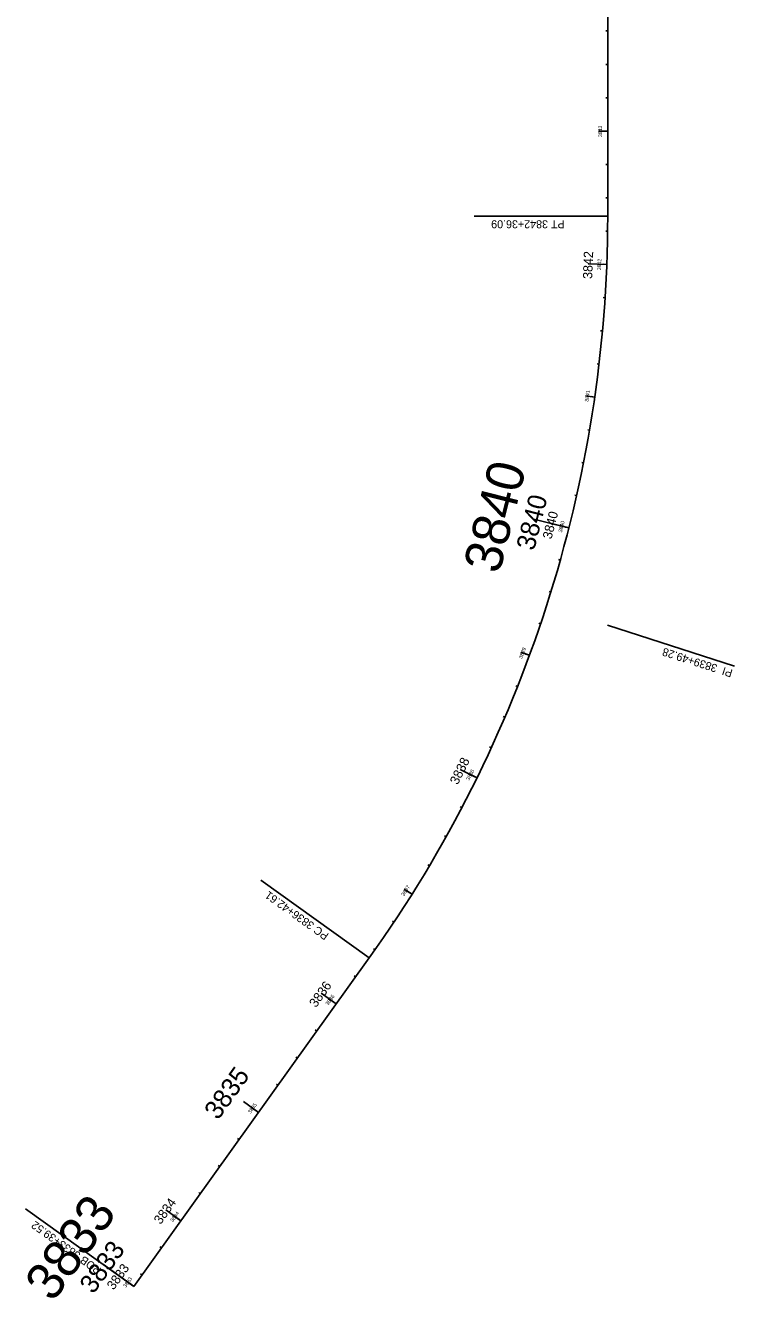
# Model space of a CAD drawing. Extents: x 536709 to 765910, y 180209 to 191282.
# Drawn here: x 594323 to 594855, y 182695 to 183650 of the extents above; entities that cross this region are included whole.
import ezdxf

# ---------------------------------------------------------------- set-up
doc = ezdxf.new("R2010")
doc.units = 0
for name, color, linetype in [('P_ALI_100', 7, 'Continuous'), ('P_ALI_100_Sta', 7, 'Continuous'), ('P_ALI_100_Tic', 7, 'Continuous'), ('P_ALI_20', 7, 'Continuous'), ('P_ALI_200', 7, 'Continuous'), ('P_ALI_200_Sta', 7, 'Continuous'), ('P_ALI_200_Tic', 7, 'Continuous'), ('P_ALI_20_Sta', 7, 'Continuous'), ('P_ALI_20_Tic', 7, 'Continuous'), ('P_ALI_50', 7, 'Continuous'), ('P_ALI_50_CPIData', 7, 'Continuous'), ('P_ALI_50_PIData', 7, 'Continuous'), ('P_ALI_50_Sta', 7, 'Continuous'), ('P_ALI_50_Tic', 7, 'Continuous')]:
    doc.layers.add(name, color=color, linetype=linetype)

msp = doc.modelspace()

# ---------------------------------------------------------------- linework, layer by layer
at = {"layer": 'P_ALI_100'}
for p, q in [((594759.83, 183506.52), (594760.03, 184249.13)), ((594759.83, 183506.52), (594760.03, 184249.13)), ((594759.83, 183506.52), (594760.03, 184249.13)), ((594759.83, 183506.52), (594760.03, 184249.13)), ((594759.83, 183506.52), (594760.03, 184249.13)), ((594759.83, 183506.52), (594760.03, 184249.13)), ((594759.83, 183506.52), (594760.03, 184249.13)), ((594759.83, 183506.52), (594760.03, 184249.13)), ((594759.83, 183506.52), (594760.03, 184249.13)), ((594759.83, 183506.52), (594760.03, 184249.13)), ((594759.83, 183506.52), (594760.03, 184249.13)), ((594404.59, 182704.19), (594581.13, 182950.56)), ((594404.59, 182704.19), (594581.13, 182950.56)), ((594404.59, 182704.19), (594581.13, 182950.56)), ((594404.59, 182704.19), (594581.13, 182950.56)), ((594404.59, 182704.19), (594581.13, 182950.56)), ((594404.59, 182704.19), (594581.13, 182950.56)), ((594404.59, 182704.19), (594581.13, 182950.56)), ((594404.59, 182704.19), (594581.13, 182950.56)), ((594404.59, 182704.19), (594581.13, 182950.56)), ((594404.59, 182704.19), (594581.13, 182950.56)), ((594404.59, 182704.19), (594581.13, 182950.56))]:
    msp.add_line(p, q, dxfattribs=at)
msp.add_arc((593804.9, 183506.77), 954.93, 324.37625, 359.98472, dxfattribs=at)
msp.add_arc((593804.9, 183506.77), 954.93, 324.37625, 359.98472, dxfattribs=at)
msp.add_arc((593804.9, 183506.77), 954.93, 324.37625, 359.98472, dxfattribs=at)
msp.add_arc((593804.9, 183506.77), 954.93, 324.37625, 359.98472, dxfattribs=at)
msp.add_arc((593804.9, 183506.77), 954.93, 324.37625, 359.98472, dxfattribs=at)
msp.add_arc((593804.9, 183506.77), 954.93, 324.37625, 359.98472, dxfattribs=at)
msp.add_arc((593804.9, 183506.77), 954.93, 324.37625, 359.98472, dxfattribs=at)
msp.add_arc((593804.9, 183506.77), 954.93, 324.37625, 359.98472, dxfattribs=at)
msp.add_arc((593804.9, 183506.77), 954.93, 324.37625, 359.98472, dxfattribs=at)
msp.add_arc((593804.9, 183506.77), 954.93, 324.37625, 359.98472, dxfattribs=at)
msp.add_arc((593804.9, 183506.77), 954.93, 324.37625, 359.98472, dxfattribs=at)
at = {"layer": 'P_ALI_100_Tic'}
for points in [[(594752.85, 183570.43), (594759.85, 183570.43)], [(594752.15, 183470.7), (594759.14, 183470.44)], [(594743.19, 183371.89), (594750.12, 183370.89)], [(594717.16, 183276.26), (594730.74, 183272.83)], [(594694.64, 183179.76), (594701.21, 183177.34)], [(594655.58, 183088.54), (594661.87, 183085.46)], [(594607.21, 183001.91), (594613.13, 182998.19)], [(594550.62, 182920), (594556.31, 182915.92)], [(594486.68, 182842.79), (594498.06, 182834.64)], [(594434.13, 182757.43), (594439.82, 182753.35)], [(594393.21, 182712.34), (594404.59, 182704.19)], [(594398.9, 182708.27), (594404.59, 182704.19)]]:
    msp.add_lwpolyline(points, dxfattribs=at)
at = {"layer": 'P_ALI_20'}
for p, q in [((594759.83, 183506.52), (594760.03, 184249.13)), ((594404.59, 182704.19), (594581.13, 182950.56))]:
    msp.add_line(p, q, dxfattribs=at)
msp.add_arc((593804.9, 183506.77), 954.93, 324.37625, 359.98472, dxfattribs=at)
at = {"layer": 'P_ALI_200'}
for p, q in [((594759.83, 183506.52), (594760.03, 184249.13)), ((594759.83, 183506.52), (594760.03, 184249.13)), ((594759.83, 183506.52), (594760.03, 184249.13)), ((594759.83, 183506.52), (594760.03, 184249.13)), ((594759.83, 183506.52), (594760.03, 184249.13)), ((594759.83, 183506.52), (594760.03, 184249.13)), ((594759.83, 183506.52), (594760.03, 184249.13)), ((594759.83, 183506.52), (594760.03, 184249.13)), ((594759.83, 183506.52), (594760.03, 184249.13)), ((594759.83, 183506.52), (594760.03, 184249.13)), ((594404.59, 182704.19), (594581.13, 182950.56)), ((594404.59, 182704.19), (594581.13, 182950.56)), ((594404.59, 182704.19), (594581.13, 182950.56)), ((594404.59, 182704.19), (594581.13, 182950.56)), ((594404.59, 182704.19), (594581.13, 182950.56)), ((594404.59, 182704.19), (594581.13, 182950.56)), ((594404.59, 182704.19), (594581.13, 182950.56)), ((594404.59, 182704.19), (594581.13, 182950.56)), ((594404.59, 182704.19), (594581.13, 182950.56)), ((594404.59, 182704.19), (594581.13, 182950.56))]:
    msp.add_line(p, q, dxfattribs=at)
msp.add_arc((593804.9, 183506.77), 954.93, 324.37625, 359.98472, dxfattribs=at)
msp.add_arc((593804.9, 183506.77), 954.93, 324.37625, 359.98472, dxfattribs=at)
msp.add_arc((593804.9, 183506.77), 954.93, 324.37625, 359.98472, dxfattribs=at)
msp.add_arc((593804.9, 183506.77), 954.93, 324.37625, 359.98472, dxfattribs=at)
msp.add_arc((593804.9, 183506.77), 954.93, 324.37625, 359.98472, dxfattribs=at)
msp.add_arc((593804.9, 183506.77), 954.93, 324.37625, 359.98472, dxfattribs=at)
msp.add_arc((593804.9, 183506.77), 954.93, 324.37625, 359.98472, dxfattribs=at)
msp.add_arc((593804.9, 183506.77), 954.93, 324.37625, 359.98472, dxfattribs=at)
msp.add_arc((593804.9, 183506.77), 954.93, 324.37625, 359.98472, dxfattribs=at)
msp.add_arc((593804.9, 183506.77), 954.93, 324.37625, 359.98472, dxfattribs=at)
at = {"layer": 'P_ALI_200_Tic'}
for points in [[(594745.15, 183470.97), (594759.14, 183470.44)], [(594745.15, 183470.97), (594759.14, 183470.44)], [(594703.59, 183279.69), (594730.74, 183272.83)], [(594703.59, 183279.69), (594730.74, 183272.83)], [(594649.3, 183091.63), (594661.87, 183085.46)], [(594649.3, 183091.63), (594661.87, 183085.46)], [(594544.93, 182924.08), (594556.31, 182915.92)], [(594544.93, 182924.08), (594556.31, 182915.92)], [(594428.44, 182761.51), (594439.82, 182753.35)], [(594428.44, 182761.51), (594439.82, 182753.35)], [(594381.83, 182720.5), (594404.59, 182704.19)], [(594381.83, 182720.5), (594404.59, 182704.19)], [(594393.21, 182712.34), (594404.59, 182704.19)], [(594393.21, 182712.34), (594404.59, 182704.19)]]:
    msp.add_lwpolyline(points, dxfattribs=at)
at = {"layer": 'P_ALI_20_Tic'}
for points in [[(594758.47, 183645.43), (594759.87, 183645.43)], [(594758.46, 183620.43), (594759.86, 183620.43)], [(594758.46, 183595.43), (594759.86, 183595.43)], [(594757.05, 183570.43), (594759.85, 183570.43)], [(594758.44, 183545.43), (594759.84, 183545.43)], [(594758.44, 183520.43), (594759.84, 183520.43)], [(594758.37, 183495.45), (594759.77, 183495.43)], [(594756.34, 183470.54), (594759.14, 183470.44)], [(594756.47, 183445.56), (594757.86, 183445.47)], [(594754.54, 183420.67), (594755.93, 183420.55)], [(594751.96, 183395.84), (594753.35, 183395.68)], [(594747.35, 183371.29), (594750.12, 183370.89)], [(594744.86, 183346.43), (594746.24, 183346.2)], [(594740.34, 183321.88), (594741.71, 183321.61)], [(594735.18, 183297.46), (594736.54, 183297.15)], [(594728.02, 183273.52), (594730.74, 183272.83)], [(594722.95, 183249.06), (594724.3, 183248.68)], [(594715.89, 183225.11), (594717.22, 183224.7)], [(594708.2, 183201.36), (594709.53, 183200.92)], [(594698.58, 183178.31), (594701.21, 183177.34)], [(594690.98, 183154.51), (594692.28, 183153.99)], [(594681.46, 183131.43), (594682.74, 183130.88)], [(594671.33, 183108.62), (594672.6, 183108.03)], [(594659.35, 183086.69), (594661.87, 183085.46)], [(594649.3, 183063.82), (594650.54, 183063.17)], [(594637.42, 183041.87), (594638.64, 183041.18)], [(594624.96, 183020.23), (594626.17, 183019.52)], [(594610.76, 182999.68), (594613.13, 182998.19)], [(594598.38, 182977.98), (594599.54, 182977.2)], [(594584.26, 182957.39), (594585.41, 182956.58)], [(594569.73, 182937.06), (594570.87, 182936.25)], [(594554.03, 182917.56), (594556.31, 182915.92)], [(594540.61, 182896.42), (594541.75, 182895.6)], [(594526.05, 182876.1), (594527.19, 182875.28)], [(594511.49, 182855.78), (594512.62, 182854.96)], [(594495.79, 182836.27), (594498.06, 182834.64)], [(594482.36, 182815.13), (594483.5, 182814.32)], [(594467.8, 182794.81), (594468.94, 182794)], [(594453.24, 182774.49), (594454.38, 182773.67)], [(594437.54, 182754.98), (594439.82, 182753.35)], [(594424.12, 182733.85), (594425.25, 182733.03)], [(594409.56, 182713.52), (594410.69, 182712.71)], [(594402.31, 182705.82), (594404.59, 182704.19)], [(594403.45, 182705), (594404.59, 182704.19)]]:
    msp.add_lwpolyline(points, dxfattribs=at)
at = {"layer": 'P_ALI_50'}
for p, q in [((594759.83, 183506.52), (594760.03, 184249.13)), ((594759.83, 183506.52), (594760.03, 184249.13)), ((594759.83, 183506.52), (594760.03, 184249.13)), ((594759.83, 183506.52), (594760.03, 184249.13)), ((594759.83, 183506.52), (594760.03, 184249.13)), ((594759.83, 183506.52), (594760.03, 184249.13)), ((594759.83, 183506.52), (594760.03, 184249.13)), ((594759.83, 183506.52), (594760.03, 184249.13)), ((594759.83, 183506.52), (594760.03, 184249.13)), ((594759.83, 183506.52), (594760.03, 184249.13)), ((594404.59, 182704.19), (594581.13, 182950.56)), ((594404.59, 182704.19), (594581.13, 182950.56)), ((594404.59, 182704.19), (594581.13, 182950.56)), ((594404.59, 182704.19), (594581.13, 182950.56)), ((594404.59, 182704.19), (594581.13, 182950.56)), ((594404.59, 182704.19), (594581.13, 182950.56)), ((594404.59, 182704.19), (594581.13, 182950.56)), ((594404.59, 182704.19), (594581.13, 182950.56)), ((594404.59, 182704.19), (594581.13, 182950.56)), ((594404.59, 182704.19), (594581.13, 182950.56))]:
    msp.add_line(p, q, dxfattribs=at)
msp.add_arc((593804.9, 183506.77), 954.93, 324.37625, 359.98472, dxfattribs=at)
msp.add_arc((593804.9, 183506.77), 954.93, 324.37625, 359.98472, dxfattribs=at)
msp.add_arc((593804.9, 183506.77), 954.93, 324.37625, 359.98472, dxfattribs=at)
msp.add_arc((593804.9, 183506.77), 954.93, 324.37625, 359.98472, dxfattribs=at)
msp.add_arc((593804.9, 183506.77), 954.93, 324.37625, 359.98472, dxfattribs=at)
msp.add_arc((593804.9, 183506.77), 954.93, 324.37625, 359.98472, dxfattribs=at)
msp.add_arc((593804.9, 183506.77), 954.93, 324.37625, 359.98472, dxfattribs=at)
msp.add_arc((593804.9, 183506.77), 954.93, 324.37625, 359.98472, dxfattribs=at)
msp.add_arc((593804.9, 183506.77), 954.93, 324.37625, 359.98472, dxfattribs=at)
msp.add_arc((593804.9, 183506.77), 954.93, 324.37625, 359.98472, dxfattribs=at)
at = {"layer": 'P_ALI_50_CPIData'}
msp.add_lwpolyline([(594759.75, 183199.84), (594854.95, 183169.24)], dxfattribs=at)
at = {"layer": 'P_ALI_50_PIData'}
for points in [[(594759.83, 183506.52), (594659.83, 183506.54)], [(594581.13, 182950.56), (594499.84, 183008.81)], [(594404.59, 182704.19), (594323.3, 182762.43)]]:
    msp.add_lwpolyline(points, dxfattribs=at)
at = {"layer": 'P_ALI_50_Tic'}
for points in [[(594756.35, 183570.43), (594759.85, 183570.43)], [(594752.15, 183470.7), (594759.14, 183470.44)], [(594746.65, 183371.39), (594750.12, 183370.89)], [(594723.95, 183274.55), (594730.74, 183272.83)], [(594697.93, 183178.55), (594701.21, 183177.34)], [(594655.58, 183088.54), (594661.87, 183085.46)], [(594610.17, 183000.05), (594613.13, 182998.19)], [(594550.62, 182920), (594556.31, 182915.92)], [(594495.22, 182836.68), (594498.06, 182834.64)], [(594434.13, 182757.43), (594439.82, 182753.35)], [(594398.9, 182708.27), (594404.59, 182704.19)], [(594401.74, 182706.23), (594404.59, 182704.19)]]:
    msp.add_lwpolyline(points, dxfattribs=at)

# ---------------------------------------------------------------- texts
at = {"layer": 'P_ALI_100_Sta'}
for s, rotation, p in [('3840', 75.81955, (594704.64, 183255.27)), ('3835', 54.37625, (594467.7, 182828.32)), ('3833', 54.37625, (594374.23, 182697.87))]:
    msp.add_text(s, height=14, rotation=rotation, dxfattribs=at).set_placement(p)
at = {"layer": 'P_ALI_200_Sta'}
for s, rotation, p in [('3840', 75.81955, (594678.54, 183237.7)), ('3840', 75.81955, (594678.54, 183237.7)), ('3833', 54.37625, (594343.87, 182691.56)), ('3833', 54.37625, (594343.87, 182691.56))]:
    msp.add_text(s, height=28, rotation=rotation, dxfattribs=at).set_placement(p)
at = {"layer": 'P_ALI_20_Sta'}
for s, rotation, p in [('3843', 89.98472, (594755.65, 183565.87)), ('3842', 87.81955, (594754.77, 183466.04)), ('3841', 81.81955, (594745.36, 183367.32)), ('3840', 75.81955, (594725.52, 183269.32)), ('3839', 69.81955, (594695.69, 183174.51)), ('3838', 63.81955, (594656.08, 183083.21)), ('3837', 57.81956, (594607.15, 182996.56)), ('3836', 54.37625, (594550.24, 182914.66)), ('3835', 54.37625, (594491.99, 182833.38)), ('3834', 54.37625, (594433.74, 182752.09)), ('3833', 54.37625, (594398.51, 182702.92))]:
    msp.add_text(s, height=2.8, rotation=rotation, dxfattribs=at).set_placement(p)
at = {"layer": 'P_ALI_50_CPIData'}
msp.add_text('PI  3839+49.28', height=6, rotation=162.18048, dxfattribs=at).set_placement((594854.04, 183166.38))
at = {"layer": 'P_ALI_50_PIData'}
for s, rotation, p in [('PT 3842+36.09', 179.98472, (594727.58, 183503.52)), ('PC 3836+42.61', 144.37625, (594551.24, 182968.29)), ('POB 3833+39.52', 144.37625, (594380.77, 182717.57))]:
    msp.add_text(s, height=6, rotation=rotation, dxfattribs=at).set_placement(p)
at = {"layer": 'P_ALI_50_Sta'}
for s, rotation, p in [('3842', 87.81955, (594748.22, 183459.44)), ('3840', 75.81955, (594717.69, 183264.05)), ('3838', 63.81955, (594647.41, 183079.85)), ('3836', 54.37625, (594541.13, 182912.77)), ('3834', 54.37625, (594424.64, 182750.19)), ('3833', 54.37625, (594389.41, 182701.03))]:
    msp.add_text(s, height=7, rotation=rotation, dxfattribs=at).set_placement(p)

doc.saveas('drawing.dxf')
